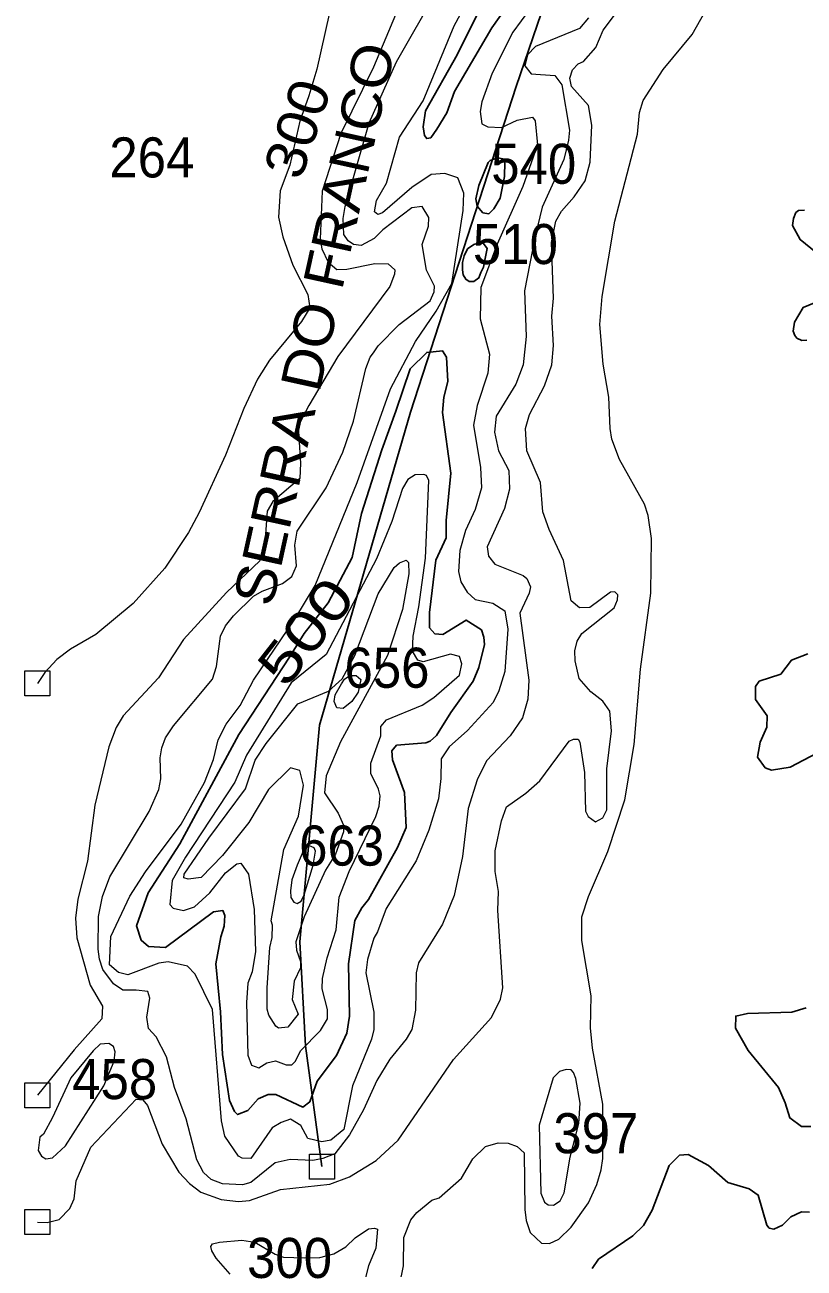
# Model space of a CAD drawing. Extents: x 499.9 to 555.3, y 9281.5 to 9336.8.
# Drawn here: x 499.95 to 503.059, y 9314.845 to 9319.808 of the extents above; entities that cross this region are included whole.
import ezdxf
from ezdxf.enums import TextEntityAlignment as Align

# ---------------------------------------------------------------- set-up
doc = ezdxf.new("R2010")
doc.units = 0
doc.header["$LTSCALE"] = 0.064
for name, color, linetype, lineweight in [('1', 7, 'Continuous', 25), ('2', 7, 'Continuous', 13), ('26', 7, 'Continuous', 25), ('62', 7, 'Continuous', 13)]:
    doc.layers.add(name, color=color, linetype=linetype, lineweight=lineweight)
doc.layers.add('21', color=7, linetype='Continuous')
doc.layers.add('61', color=7, linetype='Continuous')

msp = doc.modelspace()

# ---------------------------------------------------------------- linework, layer by layer
at = {"layer": '1'}
for points in [[(501.8641, 9320.0696), (501.6752, 9319.6888), (501.5482, 9319.4649), (501.5397, 9319.401), (501.544, 9319.3667), (501.5534, 9319.3543), (501.5695, 9319.3571), (501.5942, 9319.3914), (501.634, 9319.4569), (501.6647, 9319.5415), (501.813, 9319.7964), (501.9139, 9319.9394)], [(503.0606, 9319.0686), (503.036, 9319.0666), (503.0259, 9319.0586), (503.0166, 9319.0356), (503.0124, 9319.0077), (503.0426, 9318.9511), (503.1564, 9318.8592)], [(503.1163, 9318.7049), (503.0548, 9318.6797), (503.0201, 9318.6209), (503.0155, 9318.5847), (503.0213, 9318.5675), (503.0304, 9318.5575), (503.0499, 9318.5476), (503.0698, 9318.5492)], [(503.0733, 9317.297), (503.0082, 9317.2722), (502.9657, 9317.2166), (502.8801, 9317.188), (502.8647, 9317.1674), (502.8648, 9317.1154), (502.9116, 9317.0499), (502.91, 9317.0047), (502.8836, 9316.9449), (502.8725, 9316.8845), (502.9041, 9316.8426), (502.9287, 9316.833), (503.0034, 9316.8454), (503.1093, 9316.9009)], [(503.0674, 9315.8836), (503.0097, 9315.8666), (502.8332, 9315.8618), (502.7864, 9315.8513), (502.7848, 9315.8031), (502.8355, 9315.7139), (502.9563, 9315.5658), (502.9835, 9315.5054), (503.0018, 9315.4446), (503.048, 9315.41), (503.0853, 9315.4101)], [(502.9103, 9315.0172), (502.876, 9315.1365), (502.8402, 9315.1614), (502.7546, 9315.1864), (502.6771, 9315.2543), (502.5967, 9315.2983), (502.5619, 9315.2964), (502.5205, 9315.2554), (502.4522, 9315.0764), (502.4178, 9315.0147), (502.3755, 9314.9739), (502.2388, 9314.8813), (502.2131, 9314.8441)], [(503.0486, 9315.07), (503.0065, 9315.0505), (502.9732, 9315.0165), (502.938, 9315.0013), (502.9201, 9315.0045), (502.9103, 9315.0172)], [(503.0805, 9315.0689), (503.0486, 9315.07)]]:
    msp.add_lwpolyline(points, dxfattribs=at)
for points in [[(501.799, 9319.2581), (501.7608, 9319.1671), (501.7491, 9319.1133), (501.754, 9319.084), (501.7774, 9319.0575), (501.8009, 9319.0536), (501.8205, 9319.0742), (501.8459, 9319.1162), (501.8635, 9319.2023), (501.8655, 9319.26), (501.8576, 9319.2737), (501.8351, 9319.2767), (501.8068, 9319.2669)], [(501.7157, 9318.9142), (501.7407, 9318.9308), (501.7678, 9318.9392), (501.7802, 9318.935), (501.7948, 9318.9152), (501.7886, 9318.8881), (501.7844, 9318.8621), (501.7802, 9318.8402), (501.7688, 9318.8194), (501.7605, 9318.7976), (501.7407, 9318.783), (501.723, 9318.784), (501.7094, 9318.7923), (501.698, 9318.8101), (501.6959, 9318.8298), (501.6959, 9318.859), (501.7032, 9318.8861)], [(501.2937, 9316.2829), (501.3214, 9316.3163), (501.4362, 9316.5236), (501.4708, 9316.6042), (501.4649, 9316.7436), (501.4162, 9316.8741), (501.4138, 9316.9096), (501.4331, 9316.9332), (501.5494, 9316.9426), (501.567, 9316.9491), (501.5918, 9316.9708), (501.6489, 9317.0628), (501.7392, 9317.1881), (501.7613, 9317.2431), (501.7833, 9317.3348), (501.7817, 9317.3643), (501.7719, 9317.3927), (501.7108, 9317.432), (501.617, 9317.375), (501.5853, 9317.3771), (501.5638, 9317.4013), (501.5639, 9317.4625), (501.5893, 9317.671), (501.6306, 9317.7598), (501.6307, 9317.829), (501.6496, 9318.018), (501.6164, 9318.2611), (501.6212, 9318.3224), (501.637, 9318.3838), (501.632, 9318.4813), (501.6167, 9318.5067), (501.5536, 9318.5006), (501.4875, 9318.4354), (501.4299, 9318.2663), (501.3736, 9318.1119), (501.2929, 9317.8573), (501.2557, 9317.6823), (501.1594, 9317.5012), (501.064, 9317.378), (501.0061, 9317.2842), (500.8037, 9316.9751), (500.5679, 9316.5389), (500.442, 9316.3426), (500.396, 9316.2121), (500.4146, 9316.1539), (500.4436, 9316.1288), (500.5117, 9316.1248), (500.7026, 9316.267), (500.7398, 9316.2726), (500.7472, 9316.2526), (500.7457, 9316.2096), (500.7313, 9316.1681), (500.7125, 9316.0592), (500.73, 9315.8682), (500.7378, 9315.6979), (500.7664, 9315.5146), (500.7858, 9315.4706), (500.7984, 9315.4582), (500.8394, 9315.475), (500.8803, 9315.5215), (500.92, 9315.5386), (500.951, 9315.5385), (501.0587, 9315.4881), (501.0865, 9315.5094), (501.1167, 9315.5913), (501.1933, 9315.694), (501.2342, 9315.7824), (501.2454, 9315.8515), (501.2408, 9316.0601), (501.2661, 9316.2328)]]:
    msp.add_lwpolyline(points, close=True, dxfattribs=at)
at = {"layer": '2'}
for points in [[(502.288, 9320.3452), (502.2625, 9320.3198), (502.2136, 9320.2521), (502.1294, 9320.0971), (501.897, 9319.7786), (501.814, 9319.6155)], [(501.5169, 9320.0588), (501.3403, 9319.6386), (501.2112, 9319.3745), (501.1358, 9319.1437), (501.1279, 9318.952), (501.1345, 9318.9138), (501.1606, 9318.8609), (501.1947, 9318.8318), (501.2343, 9318.8322), (501.3466, 9318.8556), (501.4, 9318.8541), (501.426, 9318.8296), (501.4252, 9318.8126), (501.406, 9318.7634), (501.1983, 9318.4847), (501.0824, 9318.289), (501.0406, 9318.2064)], [(502.4171, 9319.5063), (502.4969, 9319.6292), (502.6121, 9319.7701), (502.6643, 9319.8616), (502.7368, 9320.0414)], [(500.3938, 9315.9546), (500.3411, 9315.9542), (500.3036, 9315.9803), (500.2605, 9316.0366), (500.2482, 9316.0786), (500.243, 9316.1185), (500.2431, 9316.2488), (500.2601, 9316.3291), (500.2896, 9316.4072), (500.4465, 9316.6673), (500.4844, 9316.7556), (500.4926, 9316.7985), (500.4897, 9316.8823), (500.496, 9316.9218), (500.5115, 9316.9625), (500.5429, 9317.0097), (500.6989, 9317.1959), (500.714, 9317.2463), (500.73, 9317.3675), (500.7506, 9317.4089), (500.7819, 9317.4496), (500.8626, 9317.527), (500.8963, 9317.5469), (500.9774, 9317.5774), (501.0149, 9317.6054), (501.0337, 9317.6484), (501.0276, 9317.7312), (501.037, 9317.787), (501.1521, 9317.9593), (501.2181, 9318.1021), (501.2611, 9318.2262), (501.3106, 9318.4363), (501.328, 9318.4816), (501.3403, 9318.499), (501.3591, 9318.5266), (501.4429, 9318.6121), (501.5672, 9318.7064), (501.5829, 9318.7417), (501.5839, 9318.7647), (501.5525, 9318.8293), (501.5357, 9318.9319), (501.5603, 9319.0041), (501.5621, 9319.0387), (501.5354, 9319.0829), (501.4933, 9319.0775), (501.3779, 9318.9896), (501.3434, 9318.9558), (501.2923, 9318.9278), (501.261, 9318.9312), (501.2404, 9318.9454), (501.2222, 9318.9712), (501.2201, 9319.0347), (501.2278, 9319.0824), (501.3235, 9319.4174), (501.4325, 9319.6608), (501.5963, 9319.9473)], [(500.4314, 9316.4277), (500.5736, 9316.6178), (500.6663, 9316.7836), (500.7031, 9316.8756), (500.7208, 9316.9535), (500.7537, 9317.0168), (500.8096, 9317.0912), (500.8615, 9317.1928), (501.0271, 9317.4359), (501.1084, 9317.5698), (501.2755, 9317.9816), (501.4082, 9318.3552), (501.509, 9318.5446), (501.5906, 9318.6656), (501.653, 9318.7761), (501.6983, 9319.0676), (501.7011, 9319.1367), (501.6769, 9319.1979), (501.6261, 9319.2147), (501.5706, 9319.21), (501.4932, 9319.1587), (501.3771, 9319.0578), (501.3585, 9319.0516), (501.3445, 9319.0623), (501.3526, 9319.1067), (501.3929, 9319.1759), (501.4443, 9319.3591), (501.5393, 9319.5047), (501.6632, 9319.8045), (501.7228, 9319.9165)], [(501.1645, 9319.8511), (501.115, 9319.6305), (501.0835, 9319.5241), (501.0467, 9319.4237), (501.0066, 9319.2477), (500.969, 9319.1453), (500.9621, 9319.0404), (500.9798, 9318.9622), (501.0189, 9318.8493), (501.0785, 9318.7323), (501.0863, 9318.678), (501.0534, 9318.6239), (500.9261, 9318.4695), (500.8782, 9318.3931), (500.8235, 9318.2772), (500.7505, 9318.09), (500.6454, 9317.8609), (500.6023, 9317.7816), (500.5081, 9317.639), (500.3819, 9317.4986), (500.2326, 9317.375), (500.1324, 9317.3161), (500.0774, 9317.2751), (500.03, 9317.2232), (500, 9317.1791)], [(500, 9315.0289), (500.0391, 9315.0279), (500.0872, 9315.0398), (500.1295, 9315.0829), (500.1466, 9315.1211), (500.1547, 9315.194), (500.2131, 9315.3283), (500.3942, 9315.5191), (500.4202, 9315.5174), (500.4395, 9315.4943), (500.4973, 9315.34), (500.5641, 9315.2285), (500.6062, 9315.1834), (500.652, 9315.1483), (500.733, 9315.1191), (500.8028, 9315.1109), (500.8461, 9315.115), (500.9701, 9315.1584), (501.1668, 9315.1806), (501.2446, 9315.2097), (501.3515, 9315.2742), (501.4388, 9315.3556), (501.6605, 9315.6782), (501.8116, 9315.8453), (501.8476, 9315.9192), (501.8565, 9315.9637), (501.8376, 9316.2726), (501.8391, 9316.3489), (501.8265, 9316.4285), (501.8265, 9316.5112), (501.8515, 9316.6305), (501.8716, 9316.6868), (501.9489, 9316.7405), (502.0046, 9316.7898), (502.1222, 9316.9483), (502.1392, 9316.9563), (502.158, 9316.9563), (502.1644, 9316.9452), (502.1829, 9316.8232), (502.1868, 9316.6691), (502.1972, 9316.6481), (502.2265, 9316.6263), (502.2556, 9316.643), (502.2716, 9316.6745), (502.272, 9316.8384), (502.2911, 9316.9902), (502.2838, 9317.0682), (502.256, 9317.1079), (502.2079, 9317.1452), (502.1611, 9317.1983), (502.1452, 9317.2689), (502.1448, 9317.3095), (502.1529, 9317.3483), (502.1715, 9317.3779), (502.3006, 9317.4808), (502.3148, 9317.5123), (502.3162, 9317.5327), (502.3044, 9317.5441), (502.2866, 9317.5432), (502.2034, 9317.4821), (502.1633, 9317.4812), (502.129, 9317.5094), (502.0987, 9317.6692), (502.0415, 9317.7938), (502.0167, 9317.8641), (502.0077, 9317.9818), (501.9528, 9318.1073), (501.9477, 9318.1964), (501.9633, 9318.2524), (502.0237, 9318.3671), (502.0525, 9318.4505), (502.0587, 9318.5286), (502.0525, 9318.6447), (502.0587, 9318.7171), (502.0513, 9318.9387), (502.0684, 9319.0246), (502.0908, 9319.064), (502.142, 9319.1221), (502.1853, 9319.1856), (502.2059, 9319.2603), (502.2115, 9319.4072), (502.1988, 9319.4866), (502.1307, 9319.5626), (502.1243, 9319.5955), (502.1346, 9319.628), (502.1569, 9319.6525), (502.1794, 9319.6611), (502.2285, 9319.7176), (502.2571, 9319.7868), (502.3028, 9319.8473)], [(502.1988, 9319.8359), (502.1628, 9319.7928), (501.9872, 9319.7213), (501.955, 9319.6881), (501.9446, 9319.6439), (501.9698, 9319.6127), (502.065, 9319.6065), (502.0926, 9319.5687), (502.1223, 9319.387), (502.1192, 9319.3474), (502.1001, 9319.271), (502.0143, 9319.08), (501.9853, 9318.9644), (501.9435, 9318.7465), (501.9505, 9318.5636), (501.9379, 9318.4505), (501.9092, 9318.3734), (501.8301, 9318.2465), (501.8233, 9318.1825), (501.8402, 9318.1077), (501.8803, 9318.0296), (501.8837, 9317.954), (501.8632, 9317.8776), (501.7949, 9317.7248), (501.7992, 9317.6866), (501.8256, 9317.6553), (501.9383, 9317.6106), (501.953, 9317.5986), (501.9678, 9317.5648), (501.9625, 9317.5392), (501.9253, 9317.459), (501.9601, 9317.1924), (501.9569, 9317.116), (501.9352, 9317.0413), (501.8865, 9316.9694), (501.7919, 9316.8699), (501.7546, 9316.7938), (501.7182, 9316.6799), (501.6957, 9316.4882), (501.6622, 9316.3323), (501.6163, 9316.2185), (501.5204, 9316.0639), (501.5111, 9316.0242), (501.508, 9315.8746), (501.4933, 9315.7976), (501.4711, 9315.7596), (501.4067, 9315.6795), (501.3539, 9315.5942), (501.3012, 9315.4767)], [(501.814, 9319.6155), (501.7726, 9319.501), (501.7661, 9319.4628), (501.7733, 9319.4124), (501.7971, 9319.4004), (501.852, 9319.3986), (501.914, 9319.4269), (501.9747, 9319.439), (501.9855, 9319.4243), (501.9949, 9319.3293), (501.9362, 9319.1628), (501.8341, 9318.9327), (501.7698, 9318.7599), (501.7661, 9318.6345), (501.8042, 9318.4931), (501.7977, 9318.4179), (501.7549, 9318.2883), (501.7405, 9318.2103), (501.7676, 9318.0416), (501.7723, 9317.9603), (501.7465, 9317.8729), (501.7081, 9317.7891), (501.6852, 9317.7099), (501.68, 9317.6261), (501.6894, 9317.5848), (501.714, 9317.5438), (501.747, 9317.5142), (501.8176, 9317.4992), (501.8645, 9317.4691), (501.8773, 9317.3954), (501.8644, 9317.2267), (501.8408, 9317.1501), (501.8183, 9317.1034), (501.7155, 9316.9908), (501.6429, 9316.926), (501.6104, 9316.8778), (501.6098, 9316.7991), (501.6004, 9316.7181), (501.5622, 9316.594), (501.5105, 9316.4715), (501.3914, 9316.2806), (501.3575, 9316.1876), (501.3426, 9316.1627), (501.317, 9316.0776), (501.3107, 9316.0236), (501.3426, 9315.8675), (501.3425, 9315.7982), (501.3327, 9315.7593), (501.2569, 9315.5729), (501.2222, 9315.3983), (501.1705, 9315.3559), (501.1345, 9315.3487), (501.0785, 9315.3624), (501.0511, 9315.4145), (501.0098, 9315.4395), (500.9727, 9315.427), (500.9363, 9315.4045), (500.8509, 9315.2833), (500.8169, 9315.2844), (500.8023, 9315.292), (500.7473, 9315.3724), (500.7347, 9315.4329), (500.6983, 9315.8777), (500.6292, 9316.0189), (500.5982, 9316.0511), (500.5214, 9316.0672), (500.4846, 9316.0619), (500.3612, 9316.0164), (500.3232, 9316.0255), (500.2874, 9316.0555), (500.2926, 9316.1694), (500.3689, 9316.3305), (500.4314, 9316.4277)], [(501.4158, 9314.6325), (501.4604, 9314.8541), (501.4622, 9314.968), (501.4892, 9315.0374), (501.5142, 9315.0673), (501.574, 9315.1168), (501.6027, 9315.1256), (501.6921, 9315.2047), (501.7374, 9315.2814), (501.7881, 9315.33), (501.8383, 9315.3451), (501.8781, 9315.3436), (501.9141, 9315.3313), (501.9421, 9315.3051), (501.9444, 9315.0792), (501.9503, 9315.0348), (501.966, 9314.9869), (502.0106, 9314.9453), (502.0435, 9314.9441), (502.0804, 9314.9601), (502.1301, 9315.0084), (502.1981, 9315.106), (502.2316, 9315.1795), (502.2497, 9315.238), (502.2561, 9315.2825), (502.2561, 9315.499), (502.2147, 9315.7226), (502.207, 9315.8039), (502.2099, 9315.9319), (502.1717, 9316.1523), (502.1722, 9316.2472), (502.1986, 9316.3291), (502.2752, 9316.5081), (502.3436, 9316.7149), (502.3803, 9316.9354), (502.4057, 9317.2363), (502.4471, 9317.5394), (502.4503, 9317.7583), (502.4372, 9317.8489), (502.4223, 9317.8944), (502.3222, 9318.0727), (502.2921, 9318.1537), (502.285, 9318.1965), (502.28, 9318.3217), (502.2578, 9318.4529), (502.2434, 9318.6118), (502.2534, 9318.7237), (502.3034, 9319.0242), (502.3942, 9319.371), (502.402, 9319.4586), (502.4171, 9319.5063)], [(501.0406, 9318.2064), (501.0497, 9318.0582), (501.0465, 9317.9969), (500.9397, 9317.9049), (500.9165, 9317.8674), (500.9066, 9317.7194)], [(500.9066, 9317.7194), (500.8872, 9317.6684), (500.7547, 9317.542), (500.583, 9317.3541), (500.4831, 9317.2021), (500.342, 9317.0497), (500.3137, 9317.003), (500.2853, 9316.9265), (500.2289, 9316.6938), (500.1998, 9316.4698), (500.1618, 9316.3178), (500.1521, 9316.2415), (500.157, 9316.1636), (500.2103, 9315.975), (500.26, 9315.8903), (500.2572, 9315.8396), (500.1468, 9315.7164), (500, 9315.5352)], [(501.0083, 9315.2792), (500.9482, 9315.2656), (500.8511, 9315.1876), (500.8181, 9315.1778), (500.7379, 9315.1817), (500.6927, 9315.1989), (500.6631, 9315.2269), (500.6357, 9315.277), (500.5929, 9315.4417), (500.5476, 9315.5659), (500.5147, 9315.6883), (500.474, 9315.7689), (500.4434, 9315.8022), (500.4371, 9315.8467), (500.4479, 9315.9223), (500.4405, 9315.9493), (500.3938, 9315.9546)], [(501.3012, 9315.4767), (501.2445, 9315.3768), (501.1868, 9315.3012), (501.1388, 9315.2826), (501.0983, 9315.2748), (501.0083, 9315.2792)], [(500.7691, 9314.8216), (500.7131, 9314.8843), (500.6962, 9314.9135), (500.6918, 9314.9321), (500.6985, 9314.9418), (500.7266, 9314.9485), (500.815, 9314.9561), (500.8675, 9314.9486), (500.9488, 9314.9006), (500.9816, 9314.8892), (501.0643, 9314.8858), (501.1266, 9314.887), (501.1832, 9314.9028), (501.2308, 9314.93), (501.268, 9314.9667), (501.3216, 9315.0021), (501.3455, 9315.0051), (501.3571, 9315.0005), (501.3501, 9314.9243), (501.3212, 9314.8543), (501.2881, 9314.7225)]]:
    msp.add_lwpolyline(points, dxfattribs=at)
for points in [[(501.1921, 9316.1952), (501.2036, 9316.3259), (501.2444, 9316.4279), (501.3502, 9316.6474), (501.363, 9316.6888), (501.3677, 9316.7308), (501.3611, 9316.7568), (501.3303, 9316.8193), (501.3299, 9316.8606), (501.3706, 9316.9698), (501.3703, 9317.0067), (501.3931, 9317.0335), (501.5354, 9317.0925), (501.5816, 9317.1235), (501.6842, 9317.2125), (501.6927, 9317.2579), (501.6845, 9317.2872), (501.6486, 9317.2958), (501.5389, 9317.2651), (501.5173, 9317.2726), (501.4961, 9317.3077), (501.499, 9317.3684), (501.5217, 9317.4852), (501.5486, 9317.6796), (501.5618, 9317.9888), (501.5524, 9318.0086), (501.542, 9318.0134), (501.5075, 9318.0116), (501.4773, 9317.9931), (501.456, 9317.9568), (501.4146, 9317.8259), (501.3525, 9317.6769), (501.1514, 9317.2951), (501.0122, 9317.1817), (500.8344, 9316.8923), (500.7879, 9316.785), (500.5908, 9316.485), (500.5374, 9316.3919), (500.5289, 9316.2962), (500.5414, 9316.2825), (500.5826, 9316.2723), (500.6264, 9316.288), (500.6878, 9316.3436), (500.7501, 9316.4231), (500.7952, 9316.4585), (500.812, 9316.4621), (500.8421, 9316.4171), (500.865, 9316.2765), (500.8698, 9316.1094), (500.8563, 9316.0275), (500.8398, 9315.9828), (500.8336, 9315.9056), (500.8397, 9315.695), (500.8543, 9315.6553), (500.883, 9315.6448), (500.9147, 9315.6644), (500.9503, 9315.6722), (500.9924, 9315.6567), (501.0145, 9315.656), (501.0294, 9315.6717), (501.0503, 9315.7129), (501.1292, 9315.7935), (501.1572, 9315.8405), (501.1578, 9315.8769), (501.1358, 9315.9598), (501.1372, 9316.0012), (501.1561, 9316.084)], [(500.9828, 9316.5156), (501.0412, 9316.6497), (501.0621, 9316.7736), (501.047, 9316.8314), (501.0101, 9316.8418), (500.922, 9316.7561), (500.8433, 9316.6243), (500.7389, 9316.4916), (500.6532, 9316.4049), (500.6009, 9316.3973), (500.5848, 9316.4034), (500.586, 9316.4181), (500.6838, 9316.5616), (500.8308, 9316.7579), (500.8691, 9316.8727), (500.9122, 9316.9397), (501.0386, 9317.0973), (501.1616, 9317.1488), (501.2163, 9317.1976), (501.267, 9317.29), (501.3593, 9317.5372), (501.4235, 9317.6415), (501.4445, 9317.6611), (501.471, 9317.6708), (501.4804, 9317.6618), (501.4819, 9317.6169), (501.457, 9317.4743), (501.3963, 9317.29), (501.209, 9316.9455), (501.1515, 9316.8097), (501.1455, 9316.7423), (501.2001, 9316.6607), (501.2212, 9316.6138), (501.2215, 9316.5861), (501.1893, 9316.4979), (501.1496, 9316.4338), (501.0648, 9316.2479), (501.0313, 9316.1476), (501.0338, 9316.1142), (501.0496, 9316.0688), (501.0497, 9316.0433), (501.0239, 9315.9907), (501.0164, 9315.9178), (501.0409, 9315.8583), (500.9993, 9315.8069), (500.9624, 9315.8034), (500.9511, 9315.8111), (500.9228, 9315.8543), (500.9172, 9315.8788), (500.9161, 9315.9637), (500.9272, 9316.1253), (500.9368, 9316.1647), (500.9382, 9316.2144), (500.9323, 9316.2316)], [(501.2133, 9317.1776), (501.2258, 9317.1963), (501.2467, 9317.2109), (501.2717, 9317.2109), (501.2904, 9317.1942), (501.28, 9317.1442), (501.255, 9317.1067), (501.2196, 9317.0797), (501.1946, 9317.0817), (501.1842, 9317.1067), (501.1883, 9317.1338)], [(501.0601, 9316.5101), (501.0357, 9316.4542), (501.0151, 9316.3946), (501.0102, 9316.3508), (501.0114, 9316.3252), (501.0224, 9316.3058), (501.0357, 9316.3009), (501.0528, 9316.3094), (501.0649, 9316.335), (501.1002, 9316.453), (501.1099, 9316.5101), (501.1039, 9316.5235), (501.0856, 9316.5308), (501.0698, 9316.5211)], [(500.1124, 9315.3333), (500.2654, 9315.573), (500.306, 9315.671), (500.3108, 9315.7085), (500.3035, 9315.7297), (500.2856, 9315.7422), (500.2509, 9315.739), (500.2219, 9315.7127), (500.1331, 9315.6048), (500.0605, 9315.4459), (500.0237, 9315.38), (500.0091, 9315.3683), (500.0028, 9315.3145), (500.0166, 9315.2927), (500.0338, 9315.2815), (500.0597, 9315.286)], [(502.0019, 9315.4159), (502.008, 9315.145), (502.0226, 9315.108), (502.0379, 9315.0972), (502.0597, 9315.097), (502.0858, 9315.1135), (502.1011, 9315.1458), (502.125, 9315.2884), (502.1604, 9315.4219), (502.1653, 9315.5036), (502.1483, 9315.6027), (502.1393, 9315.6257), (502.1298, 9315.6369), (502.11, 9315.6384), (502.0831, 9315.63), (502.0582, 9315.6054)]]:
    msp.add_lwpolyline(points, close=True, dxfattribs=at)
at = {"layer": '26'}
msp.add_lwpolyline([(501.135, 9315.2505), (501.0693, 9315.732), (501.0474, 9316.148), (501.1254, 9317.0122), (501.4885, 9318.2615), (501.9098, 9319.5617), (502.411, 9321.0288), (502.525, 9321.2265), (502.9121, 9321.8569)], dxfattribs=at)
at = {"layer": '62'}
for points in [[(499.95, 9317.2291), (500.05, 9317.2291), (500.05, 9317.1291), (499.95, 9317.1291)], [(499.95, 9315.5852), (500.05, 9315.5852), (500.05, 9315.4852), (499.95, 9315.4852)], [(501.085, 9315.3005), (501.185, 9315.3005), (501.185, 9315.2005), (501.085, 9315.2005)], [(499.95, 9315.0789), (500.05, 9315.0789), (500.05, 9314.9789), (499.95, 9314.9789)]]:
    msp.add_lwpolyline(points, close=True, dxfattribs=at)

# ---------------------------------------------------------------- texts
at = {"layer": '21', "width": 0.95}
for s, p in [('264', (500.287, 9319.1988)), ('540', (501.8106, 9319.1734)), ('510', (501.7376, 9318.8531)), ('656', (501.2252, 9317.1617)), ('663', (501.0443, 9316.4518)), ('458', (500.1388, 9315.5197)), ('397', (502.0586, 9315.3037))]:
    msp.add_text(s, height=0.16, dxfattribs=at).set_placement(p)
at = {"layer": '26', "width": 1.1}
msp.add_text('SERRA DO FRANCO', height=0.16, rotation=77.581, dxfattribs=at).set_placement((501.1826, 9318.5974), align=Align.CENTER)
at = {"layer": '61'}
for s, rotation, width, p in [('300', 71.565, 1.1, (501.1126, 9319.3685)), ('500', 52.028, 1.3, (501.1339, 9317.3376))]:
    msp.add_text(s, height=0.16, rotation=rotation, dxfattribs=dict(at, width=width)).set_placement(p, align=Align.CENTER)
at = {"layer": '61', "width": 0.95}
msp.add_text('300', height=0.16, dxfattribs=at).set_placement((501.0061, 9314.8058), align=Align.CENTER)

doc.saveas('drawing.dxf')
